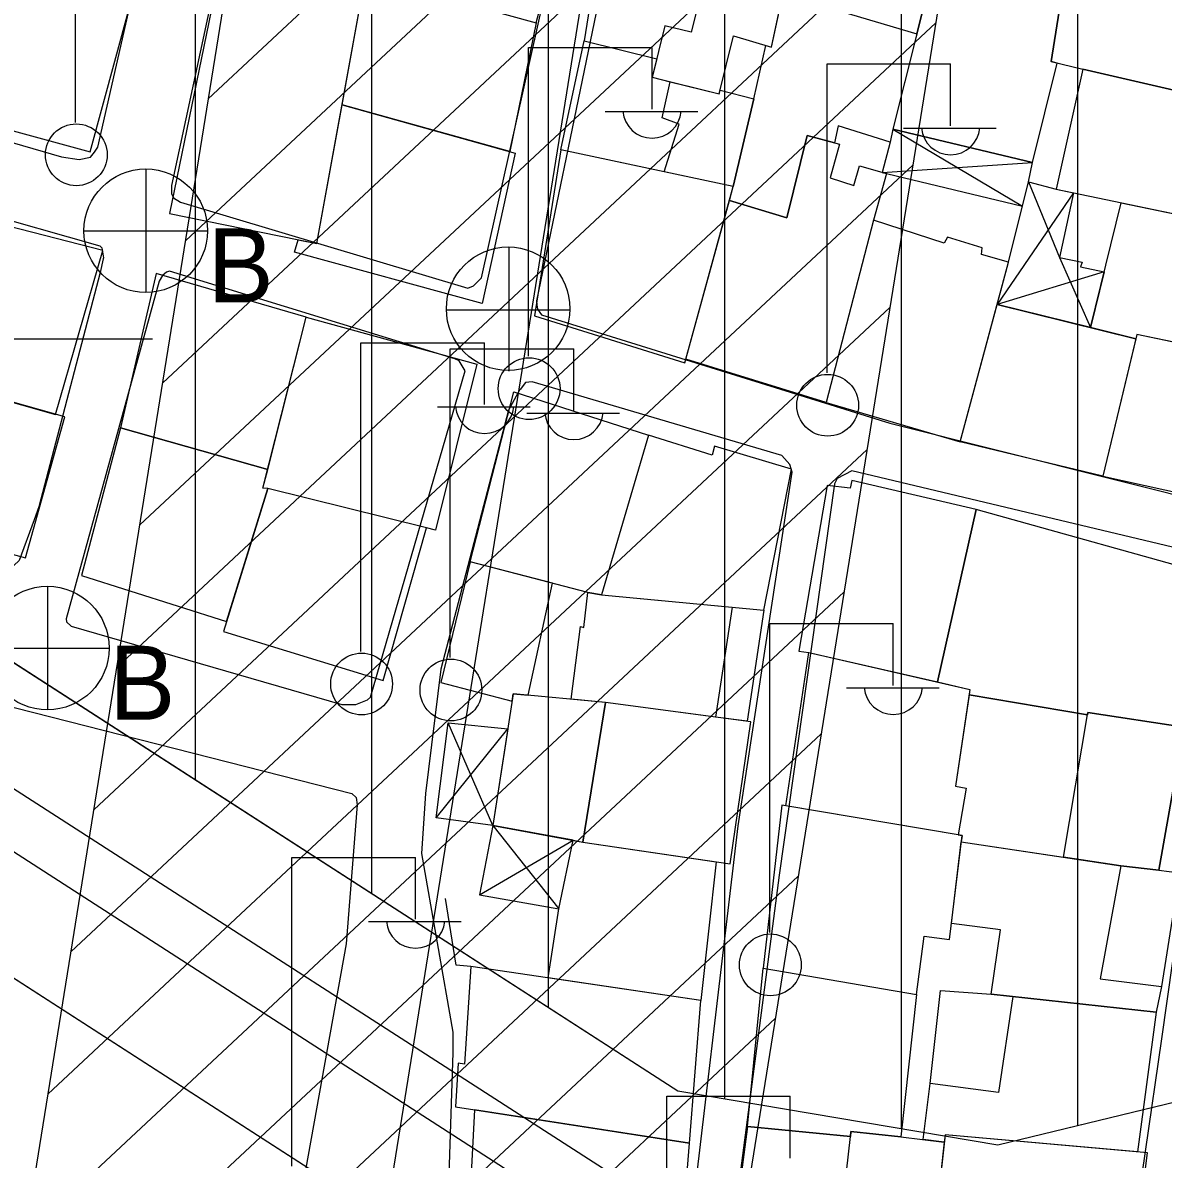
# Model space of a CAD drawing. Extents: x 417997 to 421451, y 4451742 to 4455216.
# Drawn here: x 419505.2 to 419569.8, y 4452953.5 to 4453017.9 of the extents above; entities that cross this region are included whole.
import ezdxf

# ---------------------------------------------------------------- set-up
doc = ezdxf.new("R2010")
doc.units = 0
for name, color, linetype in [('ADAKENARI', 7, 'Continuous'), ('B_Mesken', 7, 'Continuous'), ('B_Sundurma', 7, 'Continuous'), ('B_Teras', 7, 'Continuous'), ('KALDIRIM', 7, 'Continuous'), ('P_Grid', 7, 'Continuous'), ('PAFTALAMA', 7, 'Continuous'), ('PL_KON_MEV_350', 7, 'Continuous'), ('PL_SAY_KRES', 7, 'Continuous'), ('S_Elektrik_Diregi', 7, 'Continuous'), ('S_Rogar_Kapagi', 7, 'Continuous'), ('S_Rogar_Kapagi_Buski', 7, 'Continuous'), ('Sinir_Duvar_tek_tarafa_ait', 7, 'Continuous'), ('TA_ENH_154', 7, 'Continuous'), ('TA_ENH_KORUMA', 7, 'Continuous'), ('TA_ENH_TARAMA', 7, 'Continuous'), ('TR_ORTAYOGUNKONUT', 7, 'Continuous'), ('Yol_Sose', 7, 'Continuous')]:
    doc.layers.add(name, color=color, linetype=linetype)

msp = doc.modelspace()

# ---------------------------------------------------------------- linework, layer by layer
at = {"layer": 'ADAKENARI'}
for p, q in [((419799.347, 4453012.271), (419560.39, 4452954.317)), ((419799.347, 4453012.271), (419560.39, 4452954.317)), ((419542.266, 4452957.376), (419468.571, 4453004.865)), ((419542.266, 4452957.376), (419468.571, 4453004.865)), ((419487.099, 4452975.081), (419527.702, 4452948.916)), ((419487.099, 4452975.081), (419527.702, 4452948.916)), ((419560.39, 4452954.317), (419542.266, 4452957.376)), ((419560.39, 4452954.317), (419542.266, 4452957.376))]:
    msp.add_line(p, q, dxfattribs=at)
at = {"layer": 'B_Mesken'}
for points in [[(419528.488, 4453026.184), (419528.605, 4453026.731), (419525.886, 4453027.362), (419524.515, 4453020.273), (419527.133, 4453019.862), (419534.23, 4453017.894), (419535.993, 4453024.537)], [(419557.714, 4453024.881), (419557.831, 4453025.122), (419550.422, 4453027.534), (419548.389, 4453020.376), (419548.211, 4453019.541), (419555.801, 4453017.284)], [(419502.8, 4453026.792), (419499.045, 4453013.301), (419508.971, 4453010.599), (419512.64, 4453024.073), (419512.184, 4453024.185)], [(419564.442, 4453022.273), (419564.516, 4453022.868), (419557.714, 4453024.881), (419554.44, 4453011.876), (419562.359, 4453009.989), (419563.75, 4453015.627), (419563.414, 4453015.71)], [(419538.039, 4453023.757), (419536.95, 4453016.881), (419541.065, 4453015.858), (419540.808, 4453014.816), (419541.824, 4453014.565), (419544.605, 4453013.878), (419544.657, 4453014.088), (419546.569, 4453013.592), (419547.236, 4453016.623), (419547.569, 4453016.523), (419548.389, 4453020.376), (419544.129, 4453021.767)], [(419516.518, 4453021.998), (419513.457, 4453007.102), (419521.807, 4453005.392), (419524.515, 4453020.273)], [(419564.442, 4453022.273), (419563.414, 4453015.71), (419565.201, 4453015.272), (419576.498, 4453012.674), (419577.59, 4453018.692)], [(419534.23, 4453017.894), (419532.743, 4453010.605), (419523.238, 4453013.254), (419524.515, 4453020.273), (419527.133, 4453019.862)], [(419548.211, 4453019.541), (419555.801, 4453017.284), (419554.44, 4453011.876), (419554.28, 4453011.148), (419551.347, 4453012.059), (419551.135, 4453011.101), (419549.589, 4453011.518), (419548.433, 4453006.859), (419545.179, 4453007.834), (419545.396, 4453008.622), (419546.569, 4453013.592), (419547.236, 4453016.623), (419547.569, 4453016.523)], [(419535.635, 4453010.705), (419536.95, 4453016.881), (419541.065, 4453015.858), (419540.808, 4453014.816), (419541.824, 4453014.565), (419544.605, 4453013.878), (419544.657, 4453014.088), (419546.569, 4453013.592), (419545.396, 4453008.622), (419541.489, 4453009.455)], [(419565.201, 4453015.272), (419563.684, 4453008.473), (419575.752, 4453005.964), (419576.603, 4453012.628), (419576.498, 4453012.674)], [(419523.238, 4453013.254), (419533.049, 4453010.519), (419531.172, 4453002.008), (419520.551, 4453004.904), (419520.756, 4453005.607), (419521.807, 4453005.392)], [(419545.179, 4453007.834), (419548.433, 4453006.859), (419549.589, 4453011.518), (419551.419, 4453011.024), (419550.895, 4453009.113), (419552.239, 4453008.69), (419552.546, 4453009.793), (419554.08, 4453009.363), (419553.341, 4453006.725), (419550.668, 4452996.396), (419542.71, 4452998.841)], [(419535.635, 4453010.705), (419534.134, 4453001.305), (419542.654, 4452998.638), (419545.396, 4453008.622)], [(419565.633, 4453000.637), (419567.382, 4453007.704), (419575.752, 4453005.964), (419575.721, 4453005.798), (419576.28, 4453005.691), (419575.192, 4452998.799), (419568.271, 4453000.246), (419568.212, 4453000.003)], [(419506.997, 4452995.719), (419509.69, 4453005.001), (419501.664, 4453007.055), (419499.279, 4452997.906)], [(419558.259, 4452994.153), (419560.992, 4453004.346), (419559.471, 4453004.771), (419559.502, 4453005.162), (419557.544, 4453005.753), (419557.347, 4453005.422), (419553.341, 4453006.725), (419550.668, 4452996.396)], [(419521.211, 4453001.225), (419512.712, 4453003.695), (419510.695, 4452994.964), (419519.025, 4452992.591)], [(419566.334, 4452992.224), (419558.259, 4452994.153), (419560.346, 4453001.936), (419568.212, 4453000.003)], [(419519.027, 4452991.525), (419518.757, 4452991.534), (419521.211, 4453001.225), (419530.868, 4452998.556), (419528.532, 4452989.158), (419528.021, 4452989.283)], [(419568.271, 4453000.246), (419566.334, 4452992.224), (419574.466, 4452990.421), (419576.103, 4452998.609)], [(419496.964, 4452989.889), (419505.312, 4452987.588), (419507.523, 4452995.57), (419499.279, 4452997.906)], [(419537.167, 4452985.627), (419530.494, 4452987.36), (419532.974, 4452996.989), (419540.606, 4452994.533), (419537.938, 4452985.5)], [(419510.695, 4452994.964), (419508.473, 4452986.591), (419516.696, 4452983.988), (419519.027, 4452991.525), (419518.757, 4452991.534), (419519.025, 4452992.591)], [(419537.938, 4452985.5), (419547.131, 4452984.624), (419548.696, 4452992.62), (419544.343, 4452993.908), (419544.206, 4452993.397), (419540.606, 4452994.533)], [(419519.027, 4452991.525), (419516.516, 4452983.406), (419525.575, 4452980.647), (419528.021, 4452989.283)], [(419550.72, 4452991.682), (419549.11, 4452982.304), (419549.685, 4452982.226), (419556.97, 4452980.555), (419559.163, 4452990.321), (419552.124, 4452991.964), (419552.028, 4452991.532)], [(419570.947, 4452977.998), (419572.003, 4452977.855), (419573.232, 4452986.403), (419559.163, 4452990.321), (419556.97, 4452980.555), (419558.802, 4452980.135), (419558.756, 4452979.821), (419565.464, 4452978.701), (419565.485, 4452978.829), (419570.947, 4452977.998)], [(419530.494, 4452987.36), (419528.824, 4452980.524), (419532.865, 4452979.459), (419532.931, 4452979.887), (419533.781, 4452979.807), (419535.16, 4452986.148)], [(419547.131, 4452984.624), (419546.181, 4452978.33), (419544.387, 4452978.569), (419538.158, 4452979.397), (419536.211, 4452979.579), (419536.753, 4452983.697), (419536.934, 4452983.636), (419537.167, 4452985.627), (419537.938, 4452985.5)], [(419548.369, 4452973.545), (419549.685, 4452982.226), (419558.802, 4452980.135), (419557.998, 4452974.644), (419558.592, 4452974.543), (419558.146, 4452971.9)], [(419532.931, 4452979.887), (419531.779, 4452972.413), (419536.884, 4452971.487), (419538.158, 4452979.397)], [(419536.884, 4452971.487), (419545.219, 4452970.256), (419546.403, 4452978.301), (419538.158, 4452979.397)], [(419565.464, 4452978.701), (419558.756, 4452979.821), (419557.998, 4452974.644), (419558.592, 4452974.543), (419558.146, 4452971.9), (419558.358, 4452971.864), (419558.315, 4452971.501), (419564.103, 4452970.633), (419567.347, 4452970.146), (419569.515, 4452969.892), (419570.947, 4452977.998), (419565.485, 4452978.829)], [(419548.152, 4452973.582), (419547.09, 4452964.33), (419555.784, 4452962.852), (419556.217, 4452966.15), (419557.65, 4452965.968), (419558.358, 4452971.864)], [(419544.439, 4452970.371), (419543.566, 4452962.5), (419534.911, 4452963.785), (419535.515, 4452967.694), (419536.33, 4452971.588), (419536.884, 4452971.487)], [(419558.315, 4452971.501), (419564.103, 4452970.633), (419567.347, 4452970.146), (419569.515, 4452969.892), (419570.678, 4452969.746), (419569.651, 4452963.304), (419569.359, 4452961.846), (419560.017, 4452962.858), (419560.543, 4452966.509), (419557.759, 4452966.871)], [(419529.671, 4452956.475), (419542.921, 4452954.418), (419543.566, 4452962.5), (419530.526, 4452964.437), (419530.176, 4452958.898), (419529.814, 4452958.959)], [(419546.214, 4452955.376), (419547.09, 4452964.33), (419555.784, 4452962.852), (419554.897, 4452954.772), (419552.058, 4452955.09), (419552.048, 4452954.792)], [(419569.359, 4452961.846), (419568.297, 4452953.923), (419557.398, 4452954.897), (419557.352, 4452954.485), (419556.149, 4452954.625), (419556.563, 4452957.796), (419557.143, 4452963.077), (419560.017, 4452962.858)], [(419530.744, 4452956.309), (419530.325, 4452948.351), (419542.281, 4452946.414), (419542.921, 4452954.418)], [(419546.214, 4452955.376), (419552.048, 4452954.792), (419552.058, 4452955.09), (419554.897, 4452954.772), (419557.352, 4452954.485), (419556.514, 4452946.925), (419555.38, 4452947.05), (419555.399, 4452947.208), (419551.256, 4452947.802), (419545.301, 4452948.462)], [(419556.514, 4452946.925), (419567.695, 4452944.662), (419568.863, 4452953.872), (419557.398, 4452954.897)]]:
    msp.add_lwpolyline(points, close=True, dxfattribs=at)
at = {"layer": 'B_Sundurma'}
for p, q in [((419554.44, 4453011.876), (419561.781, 4453007.509)), ((419553.834, 4453009.432), (419562.359, 4453009.989)), ((419562.128, 4453008.899), (419563.882, 4453004.605)), ((419564.682, 4453008.266), (419560.346, 4453001.936)), ((419563.882, 4453004.605), (419565.633, 4453000.637)), ((419566.414, 4453003.793), (419560.346, 4453001.936)), ((419531.779, 4452972.413), (419529.244, 4452978.231)), ((419528.561, 4452972.857), (419532.625, 4452977.903)), ((419531.779, 4452972.413), (419535.515, 4452967.694)), ((419531.026, 4452968.493), (419536.33, 4452971.588))]:
    msp.add_line(p, q, dxfattribs=at)
for points in [[(419554.44, 4453011.876), (419554.28, 4453011.148), (419553.834, 4453009.432), (419554.08, 4453009.363), (419561.781, 4453007.509), (419562.128, 4453008.899), (419562.359, 4453009.989)], [(419560.992, 4453004.346), (419562.128, 4453008.899), (419563.684, 4453008.473), (419564.682, 4453008.266), (419563.882, 4453004.605), (419565.169, 4453004.346), (419565.062, 4453004.073), (419566.414, 4453003.793), (419565.633, 4453000.637), (419560.346, 4453001.936)], [(419531.779, 4452972.413), (419528.561, 4452972.857), (419529.244, 4452978.231), (419532.625, 4452977.903)], [(419531.779, 4452972.413), (419531.026, 4452968.493), (419535.515, 4452967.694), (419536.33, 4452971.588)]]:
    msp.add_lwpolyline(points, close=True, dxfattribs=at)
at = {"layer": 'B_Teras'}
for points in [[(419544.129, 4453021.767), (419543.009, 4453017.378), (419541.527, 4453017.725), (419540.808, 4453014.816), (419544.605, 4453013.878), (419545.418, 4453017.164), (419547.569, 4453016.523), (419548.389, 4453020.376)], [(419544.657, 4453014.088), (419546.569, 4453013.592), (419545.396, 4453008.622), (419541.489, 4453009.455), (419542.338, 4453012.17), (419541.372, 4453012.527), (419541.824, 4453014.565), (419544.605, 4453013.878)], [(419545.34, 4452984.795), (419544.387, 4452978.569), (419538.158, 4452979.397), (419536.211, 4452979.579), (419536.753, 4452983.697), (419536.934, 4452983.636), (419537.167, 4452985.627), (419537.938, 4452985.5)], [(419565.485, 4452978.829), (419570.947, 4452977.998), (419569.515, 4452969.892), (419567.347, 4452970.146), (419564.103, 4452970.633)], [(419558.315, 4452971.501), (419567.347, 4452970.146), (419566.187, 4452963.743), (419569.651, 4452963.304), (419569.359, 4452961.846), (419560.017, 4452962.858), (419560.543, 4452966.509), (419557.759, 4452966.871)], [(419560.017, 4452962.858), (419561.234, 4452962.726), (419560.432, 4452957.29), (419556.563, 4452957.796), (419557.143, 4452963.077)], [(419551.256, 4452947.802), (419552.048, 4452954.792), (419546.214, 4452955.376), (419545.301, 4452948.462)]]:
    msp.add_lwpolyline(points, close=True, dxfattribs=at)
at = {"layer": 'KALDIRIM'}
for p, q in [((419553.898, 4452939.173), (419461.742, 4452998.559)), ((419553.898, 4452939.173), (419461.742, 4452998.559)), ((419539.418, 4452952.073), (419467.675, 4452998.305)), ((419539.418, 4452952.073), (419467.675, 4452998.305))]:
    msp.add_line(p, q, dxfattribs=at)
at = {"layer": 'P_Grid'}
msp.add_line((419503.125, 4453000), (419512.5, 4453000), dxfattribs=at)
at = {"layer": 'PAFTALAMA'}
msp.add_line((419502.5, 4453000), (419512.5, 4453000), dxfattribs=at)
msp.add_line((419502.5, 4453000), (419512.5, 4453000), dxfattribs=at)
at = {"layer": 'PL_KON_MEV_350'}
msp.add_lwpolyline([(419823.627, 4453240.148), (419822.565, 4453223.702), (419795.483, 4453226.221), (419799.027, 4453156.869), (419756.504, 4453159.4), (419758.023, 4453124.471), (419816.158, 4453124.471), (419809.709, 4453024.608), (419799.347, 4453012.271), (419707.401, 4453034.871), (419706.895, 4453052.588), (419682.596, 4453052.082), (419684.115, 4453033.858), (419707.401, 4453034.871), (419799.347, 4453012.271), (419560.39, 4452954.317), (419542.266, 4452957.376), (419468.571, 4453004.865), (419464.929, 4453019.074), (419512.36, 4453106.601), (419622.453, 4453235.699), (419667.916, 4453224.196), (419710.945, 4453222.677), (419709.932, 4453261.656)], dxfattribs=at)
at = {"layer": 'PL_SAY_KRES'}
msp.add_lwpolyline([(419487.099, 4452975.081), (419527.702, 4452948.916), (419502.486, 4452912.927), (419465.555, 4452938.384)], close=True, dxfattribs=at)
msp.add_lwpolyline([(419487.099, 4452975.081), (419527.702, 4452948.916), (419502.486, 4452912.927), (419465.555, 4452938.384)], close=True, dxfattribs=at)
at = {"layer": 'S_Elektrik_Diregi'}
for p, q in [((419508.145, 4453012.261), (419508.145, 4453029.761)), ((419533.799, 4452999.012), (419533.799, 4453016.512)), ((419533.799, 4453016.512), (419540.799, 4453016.512)), ((419540.799, 4453013.012), (419540.799, 4453016.512)), ((419550.711, 4452998.071), (419550.711, 4453015.571)), ((419550.711, 4453015.571), (419557.711, 4453015.571)), ((419557.711, 4453012.071), (419557.711, 4453015.571)), ((419538.139, 4453012.872), (419543.389, 4453012.872)), ((419555.051, 4453011.931), (419560.301, 4453011.931)), ((419524.308, 4452982.279), (419524.308, 4452999.779)), ((419524.308, 4452999.779), (419531.308, 4452999.779)), ((419529.368, 4452981.934), (419529.368, 4452999.434)), ((419529.368, 4452999.434), (419536.368, 4452999.434)), ((419531.308, 4452996.279), (419531.308, 4452999.779)), ((419536.368, 4452995.934), (419536.368, 4452999.434)), ((419528.648, 4452996.139), (419533.898, 4452996.139)), ((419533.708, 4452995.794), (419538.958, 4452995.794)), ((419547.467, 4452966.362), (419547.467, 4452983.862)), ((419547.467, 4452983.862), (419554.467, 4452983.862)), ((419554.467, 4452980.362), (419554.467, 4452983.862)), ((419551.807, 4452980.222), (419557.057, 4452980.222)), ((419520.399, 4452953.117), (419520.399, 4452970.617)), ((419520.399, 4452970.617), (419527.399, 4452970.617)), ((419527.399, 4452967.117), (419527.399, 4452970.617)), ((419524.739, 4452966.977), (419529.989, 4452966.977)), ((419541.628, 4452957.077), (419548.628, 4452957.077)), ((419541.628, 4452939.577), (419541.628, 4452957.077)), ((419548.628, 4452953.577), (419548.628, 4452957.077))]:
    msp.add_line(p, q, dxfattribs=at)
for centre in [(419508.181, 4453010.425), (419533.835, 4452997.176), (419550.747, 4452996.235), (419524.344, 4452980.443), (419529.404, 4452980.098), (419547.503, 4452964.526)]:
    msp.add_circle(centre, 1.75, dxfattribs=at)
for centre in [(419540.8, 4453013.025), (419557.711, 4453012.084), (419531.309, 4452996.291), (419536.369, 4452995.947), (419554.468, 4452980.375), (419527.399, 4452967.13)]:
    msp.add_arc(centre, 1.658, 184.83843, 355.14641, dxfattribs=at)
at = {"layer": 'S_Rogar_Kapagi'}
for p, q in [((419532.699, 4452998.175), (419532.699, 4453005.175)), ((419529.129, 4453001.64), (419536.129, 4453001.64))]:
    msp.add_line(p, q, dxfattribs=at)
msp.add_circle((419532.646, 4453001.704), 3.5, dxfattribs=at)
at = {"layer": 'S_Rogar_Kapagi_Buski'}
for p, q in [((419512.113, 4453009.625), (419512.113, 4453002.625)), ((419508.613, 4453006.125), (419515.613, 4453006.125)), ((419506.543, 4452985.975), (419506.543, 4452978.975)), ((419503.043, 4452982.475), (419510.043, 4452982.475))]:
    msp.add_line(p, q, dxfattribs=at)
for centre in [(419512.113, 4453006.125), (419506.543, 4452982.475)]:
    msp.add_circle(centre, 3.5, dxfattribs=at)
at = {"layer": 'Sinir_Duvar_tek_tarafa_ait'}
msp.add_lwpolyline([(419530.526, 4452964.437), (419529.71, 4452964.514), (419529.092, 4452968.292)], dxfattribs=at)
at = {"layer": 'TA_ENH_154'}
msp.add_lwpolyline([(421244.229, 4452871.733), (420603.453, 4452866.932), (420104.111, 4452747.147), (419709.07, 4452649.72), (419353.297, 4452559.565), (419284.532, 4452601.288), (419287.681, 4452599.871), (419484.079, 4452691.722), (419833.947, 4454863.938), (419862.826, 4455014.236)], dxfattribs=at)
msp.add_lwpolyline([(421244.229, 4452871.733), (420603.453, 4452866.932), (420104.111, 4452747.147), (419709.07, 4452649.72), (419353.297, 4452559.565), (419284.532, 4452601.288), (419287.681, 4452599.871), (419484.079, 4452691.722), (419833.947, 4454863.938), (419862.826, 4455014.236)], dxfattribs=at)
at = {"layer": 'TA_ENH_KORUMA'}
msp.add_line((419466.015, 4452705.355), (419814.248, 4454867.416), dxfattribs=at)
msp.add_line((419466.015, 4452705.355), (419814.248, 4454867.416), dxfattribs=at)
msp.add_lwpolyline([(419883.153, 4455014.021), (419853.647, 4454860.459), (419502.143, 4452678.088), (419329.549, 4452597.37), (419356.508, 4452581.013), (419704.218, 4452669.124), (420099.383, 4452766.582), (420601.013, 4452886.916), (421244.438, 4452891.737)], dxfattribs=at)
msp.add_lwpolyline([(419883.153, 4455014.021), (419853.647, 4454860.459), (419502.143, 4452678.088), (419329.549, 4452597.37), (419356.508, 4452581.013), (419704.218, 4452669.124), (420099.383, 4452766.582), (420601.013, 4452886.916), (421244.438, 4452891.737)], dxfattribs=at)
at = {"layer": 'TA_ENH_TARAMA'}
for p, q in [((419515.661, 4453013.603), (419563.361, 4453058.181)), ((419515.661, 4453013.603), (419563.361, 4453058.181)), ((419514.364, 4453005.546), (419562.063, 4453050.124)), ((419514.364, 4453005.546), (419562.063, 4453050.124)), ((419513.066, 4452997.488), (419560.765, 4453042.067)), ((419513.066, 4452997.488), (419560.765, 4453042.067)), ((419511.768, 4452989.431), (419559.468, 4453034.01)), ((419511.768, 4452989.431), (419559.468, 4453034.01)), ((419510.47, 4452981.374), (419558.17, 4453025.953)), ((419510.47, 4452981.374), (419558.17, 4453025.953)), ((419509.173, 4452973.317), (419556.872, 4453017.896)), ((419509.173, 4452973.317), (419556.872, 4453017.896)), ((419507.875, 4452965.26), (419555.575, 4453009.839)), ((419507.875, 4452965.26), (419555.575, 4453009.839)), ((419506.577, 4452957.203), (419554.277, 4453001.781)), ((419506.577, 4452957.203), (419554.277, 4453001.781)), ((419505.28, 4452949.146), (419552.979, 4452993.724)), ((419505.28, 4452949.146), (419552.979, 4452993.724)), ((419503.982, 4452941.088), (419551.682, 4452985.667)), ((419503.982, 4452941.088), (419551.682, 4452985.667)), ((419502.684, 4452933.031), (419550.384, 4452977.61)), ((419502.684, 4452933.031), (419550.384, 4452977.61)), ((419501.387, 4452924.974), (419549.086, 4452969.553)), ((419501.387, 4452924.974), (419549.086, 4452969.553)), ((419500.089, 4452916.917), (419547.788, 4452961.496)), ((419500.089, 4452916.917), (419547.788, 4452961.496))]:
    msp.add_line(p, q, dxfattribs=at)
at = {"layer": 'TR_ORTAYOGUNKONUT'}
for p, q in [((419564.929, 4452955.417), (419564.929, 4453168.245)), ((419564.929, 4452955.417), (419564.929, 4453168.245)), ((419554.929, 4452955.238), (419554.929, 4453156.519)), ((419554.929, 4452955.238), (419554.929, 4453156.519)), ((419544.929, 4452956.927), (419544.929, 4453144.793)), ((419544.929, 4452956.927), (419544.929, 4453144.793)), ((419534.929, 4452962.104), (419534.929, 4453133.066)), ((419534.929, 4452962.104), (419534.929, 4453133.066)), ((419524.929, 4452968.548), (419524.929, 4453121.34)), ((419524.929, 4452968.548), (419524.929, 4453121.34)), ((419514.929, 4452974.992), (419514.929, 4453109.614)), ((419514.929, 4452974.992), (419514.929, 4453109.614))]:
    msp.add_line(p, q, dxfattribs=at)
at = {"layer": 'Yol_Sose'}
for points in [[(419461.74, 4453045.759), (419451.092, 4453031.346), (419450.828, 4453030.718), (419450.879, 4453030.369), (419451.852, 4453028.937), (419454.185, 4453026.944), (419454.986, 4453026.507), (419461.368, 4453024.228), (419497, 4453013.32), (419507.343, 4453010.32), (419508.337, 4453010.161), (419508.984, 4453010.283), (419509.212, 4453010.579), (419509.404, 4453010.858), (419515.836, 4453039.166), (419515.576, 4453039.882), (419515.28, 4453040.092), (419499.02, 4453045.361)], [(419534.544, 4453001.367), (419554.274, 4452995.219), (419573.164, 4452990.474), (419573.695, 4452990.428), (419574.059, 4452990.518), (419574.211, 4452990.609), (419574.333, 4452990.866), (419578.567, 4453018.625), (419578.553, 4453019.08), (419578.433, 4453019.398), (419578.176, 4453019.58), (419540.781, 4453031.695), (419540.554, 4453031.68), (419540.341, 4453031.559), (419540.341, 4453031.559), (419534.253, 4453002.16), (419534.268, 4453001.918), (419534.312, 4453001.676)], [(419453.478, 4453022.128), (419474.278, 4453015.271), (419509.506, 4453005.267), (419509.628, 4453005.145), (419509.731, 4453004.587), (419509.713, 4453004.534), (419509.536, 4453003.75), (419506.053, 4452990.48), (419505.786, 4452989.751), (419504.941, 4452987.434), (419504.643, 4452987.156), (419504.242, 4452987.07), (419481.415, 4452992.709), (419449.367, 4453002.36)], [(419534.312, 4453001.676), (419534.544, 4453001.367)], [(419542.634, 4452946.687), (419545.684, 4452972.408), (419548.746, 4452992.445), (419548.596, 4452992.869), (419548.144, 4452993.384), (419533.999, 4452997.557), (419533.636, 4452997.527), (419533.332, 4452997.135), (419533.301, 4452997.135), (419532.662, 4452995.957), (419528.832, 4452981.273), (419527.961, 4452974.23), (419527.738, 4452970.845), (419529.52, 4452960.713), (419529.516, 4452959.564), (419529.213, 4452950.314)], [(419545.607, 4452951.259), (419544.285, 4452940.982), (419544.373, 4452940.209), (419544.585, 4452939.997), (419551.671, 4452938.469), (419564.871, 4452934.31), (419565.416, 4452934.219), (419565.78, 4452934.354), (419565.978, 4452934.793), (419569.687, 4452960.334), (419573.414, 4452986.745), (419573.052, 4452987.533), (419552.115, 4452992.512), (419551.294, 4452992.09), (419551.142, 4452991.787), (419548.005, 4452969.617)], [(419426.801, 4452873.938), (419427.046, 4452874.478), (419446.472, 4452902.905), (419446.925, 4452903.588), (419478.025, 4452953.012), (419494.275, 4452979.621), (419495.341, 4452980.299), (419496.44, 4452980.506), (419500.71, 4452980.115), (419523.792, 4452974.234), (419524.035, 4452974.007), (419524.086, 4452973.589), (419523.467, 4452965.714), (419521.016, 4452952.059), (419520.521, 4452949.952), (419519.905, 4452948.281), (419518.939, 4452946.226), (419507.508, 4452926.961), (419490.831, 4452898.122), (419475.772, 4452873.2)], [(419548.005, 4452969.617), (419545.607, 4452951.259)]]:
    msp.add_lwpolyline(points, dxfattribs=at)
for points in [[(419514.093, 4453007.746), (419530.372, 4453002.871), (419530.686, 4453002.992), (419531.142, 4453003.462), (419537.517, 4453032.042), (419537.396, 4453032.391), (419537.048, 4453032.705), (419520.228, 4453037.494), (419519.949, 4453037.372), (419519.687, 4453037.163), (419513.573, 4453008.688), (419513.571, 4453008.235), (419513.693, 4453007.99)], [(419507.896, 4452983.718), (419523.216, 4452979.276), (419524.017, 4452979.275), (419524.682, 4452979.548), (419524.843, 4452979.685), (419530.214, 4452998.178), (419529.873, 4452998.751), (419529.621, 4452998.865), (419513.456, 4453003.835), (419513.296, 4453003.767), (419513.066, 4453003.584), (419512.882, 4453003.264), (419507.6, 4452984.131), (419507.622, 4452983.971)]]:
    msp.add_lwpolyline(points, close=True, dxfattribs=at)

# ---------------------------------------------------------------- texts
at = {"layer": 'S_Rogar_Kapagi_Buski'}
for p in [(419515.613, 4453002.06), (419510.043, 4452978.41)]:
    msp.add_text('B', height=4.2, dxfattribs=at).set_placement(p)

doc.saveas('drawing.dxf')
